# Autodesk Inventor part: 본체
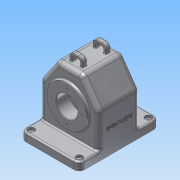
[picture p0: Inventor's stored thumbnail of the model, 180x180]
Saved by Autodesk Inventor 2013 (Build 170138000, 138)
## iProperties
Created: 2016-12
Part Number: 본체
Material: 알루미늄 6061
Document SubType Name: Modeling
Designer: Administrator
Density: 2.71 g/cm^3
Mass: 1063.78 g
Surface Area: 1146.71 cm^2
Volume: 392.539 cm^3
Author: Administrator
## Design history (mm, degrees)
sketch "스케치1"
  geometry: L1 (-65, 55)-(65, 55); L2 (75, 45)-(75, -45); L3 (65, -55)-(-65, -55); L4 (-75, -45)-(-75, 45); A1 r 10 centre (-65, 45) between (-65, 55) and (-75, 45); A2 r 10 centre (65, 45) between (75, 45) and (65, 55); A3 r 10 centre (-65, -45) between (-75, -45) and (-65, -55); A4 r 10 centre (65, -45) between (65, -55) and (75, -45); 6 further points
  constraints: 8 end point, 8 point on circle, 8 tangent, 6 point on line, 4 centre point, 3 equal radius, 2 midpoint, 2 parallel, 1 horizontal, 1 horizontal alignment, 1 perpendicular, 1 vertical alignment
  dimensions: "d0" = 150 distance of point (-75, 55) point (75, 55); "d2" = 110 distance of point (75, 55) point (75, -55); "d3" = 10 radius of A1
extrude "돌출1" new body sketch "스케치1" distance "d4" = 15; taper "d5" = 0 deg
sketch "스케치2"
  geometry: L1 (-55, 0)-(-55, 15) reference; L2 (-55, 15)-(55, 15) reference; L3 (55, 15)-(55, 0) reference; L4 (55, 0)-(-55, 0) reference; L5 (-55, 15)-(-55, 80); L6 (-23.491, 125)-(23.491, 125); L7 (55, 80)-(55, 15); L8 (-23.491, 125)-(-55, 80); L9 (23.491, 125)-(55, 80); 3 further points
  constraints: 10 end point, 2 midpoint, 2 perpendicular, 1 horizontal alignment, 1 point on line, 1 vertical, 1 vertical alignment
  dimensions: "d6" = 125 distance between parallel lines of L4 L6; "d7" = 80 distance from line of L7.start L4; "d24" = 35 deg angle of L5 L8; "d25" = 35 deg angle of L7 L9
extrude "돌출2" join sketch "스케치2" stored distance "d12" = 77; taper "d13" = 0 deg
sketch "스케치3"
  geometry: L1 (-15, -55)-(-15, 55) reference; L2 (-80, 55)-(-15, 55) reference; L3 (-15, -55)-(-80, -55) reference; L4 (0, -55)-(-15, -55) reference; L5 (0, 55)-(0, -55) reference; L6 (-15, 55)-(0, 55) reference; L7 (-125, -23.491)-(-125, 23.491) reference; L8 (-125, 23.491)-(-80, 55) reference; L9 (-80, -55)-(-125, -23.491) reference; C1 r 37.5 at (-65, 0); 2 further points
  constraints: 1 centre point, 1 horizontal alignment, 1 midpoint
  dimensions: "d15" = 65 distance from line of L5 C1.centre; "d16" = 75 diameter of C1
extrude "돌출3" join sketch "스케치3" distance "d17" = 5; taper "d18" = 0 deg
sketch "스케치4"
  geometry: L1 (15, 55)-(15, -55) reference; L2 (80, -55)-(15, -55) reference; L3 (15, 55)-(80, 55) reference; L4 (0, 55)-(15, 55) reference; L5 (0, -55)-(0, 55) reference; L6 (15, -55)-(0, -55) reference; L7 (125, 23.491)-(125, -23.491) reference; L8 (125, -23.491)-(80, -55) reference; L9 (80, 55)-(125, 23.491) reference; C1 r 31 at (65, 0); 2 further points
  constraints: 1 centre point, 1 horizontal alignment, 1 midpoint
  dimensions: "d19" = 62 diameter of C1; "d21" = 65 distance of point (0, 0) C1.centre
extrude "돌출4" join sketch "스케치4" distance "d22" = 10; taper "d23" = 0 deg
sketch "스케치6"
  geometry: L1 (-23.491, 125)-(23.491, 125) reference; L2 (23.491, 125)-(55, 80) reference; L3 (55, 80)-(55, 0) reference; L4 (55, 0)-(-55, 0) reference; L5 (-55, 0)-(-55, 80) reference; L6 (-55, 80)-(-23.491, 125) reference; L7 (50, 78.424)-(20.888, 120); L8 (20.888, 120)-(-20.888, 120); L9 (-20.888, 120)-(-50, 78.424); L10 (-50, 78.424)-(-50, 0); L11 (50, 0)-(50, 78.424); 1 further point
  constraints: 10 end point, 2 point on line, 2 other
  dimensions: "d26" = 5 distance between parallel lines of L1 L8; "d27" = 5 distance between parallel lines of L5 L10; "d28" = 5 distance between parallel lines of L11 L3
extrude "돌출5" cut sketch "스케치6" stored distance "d29" = 67; taper "d30" = 0 deg
sketch "스케치7"
  geometry: L1 (-33.5, 78.424)-(-33.5, 0) reference; L2 (-33.5, 120)-(-33.5, 78.424) reference; L3 (-43.5, 102.5)-(-43.5, 27.5) reference; L4 (33.5, 0)-(-33.5, 0) reference; L5 (-38.5, 65)-(-19.5, 65); L6 (-38.5, 111)-(-19.5, 92); L7 (-19.5, 92)-(-19.5, 65); L8 (-38.5, 125)-(-38.5, 80) reference; L9 (-38.5, 111)-(-38.5, 65); 2 further points
  constraints: 8 end point, 1 collinear, 1 horizontal alignment, 1 midpoint, 1 parallel, 1 perpendicular, 1 point on line
  dimensions: "d39" = 24 distance between parallel lines of L7 L3; "d40" = 54 diameter of L6.end L5; "d41" = 45 deg angle of L7 L6
revolve "회전1" sketch "스케치7" stored, may be unused: angle "d42" = 90 deg
hole "구멍1" diameter "d45" = 40; stored, may be unused: countersink angle "d49" = 90 deg, drill point angle "d51" = 0 deg; dims "d43" = 10, "d44" = 10, "d46" = 6, "d47" = 4, "d48" = 2, "d50" = 8
hole "구멍2" diameter "d54" = 5; stored, may be unused: countersink angle "d58" = 90 deg, drill point angle "d60" = 0 deg; dims "d52" = 10, "d53" = 10, "d55" = 6, "d56" = 12, "d57" = 5, "d59" = 8
hole "구멍3" diameter "d63" = 5; stored, may be unused: countersink angle "d67" = 90 deg, drill point angle "d69" = 0 deg; dims "d61" = 10, "d62" = 10, "d64" = 6, "d65" = 12, "d66" = 5, "d68" = 8
hole "구멍4" diameter "d72" = 5; stored, may be unused: countersink angle "d76" = 90 deg, drill point angle "d78" = 0 deg; dims "d70" = 10, "d71" = 10, "d73" = 6, "d74" = 12, "d75" = 5, "d77" = 8
hole "구멍5" diameter "d81" = 5; stored, may be unused: countersink angle "d85" = 90 deg, drill point angle "d87" = 0 deg; dims "d79" = 10, "d80" = 10, "d82" = 6, "d83" = 12, "d84" = 5, "d86" = 8
node "작업 평면1"
sketch "스케치9"
  geometry: L1 (103.5, -15)-(103.5, -80) reference; L2 (130, 0)-(0, 0) reference; 3 further points
  constraints: 1 coincident, 1 other
  dimensions: "d102" = 38.5 distance from line of point (65, -45) L1; "d103" = 45 distance from line of L2 point (65, -45)
feature "엠보싱1" sketch "스케치9" dims "d6" = 125, "d7" = 80, "d24" = 35 deg, "d25" = 35 deg, "d104" = 0.5, "d105" = 0
chamfer "모따기1" distance "d106" = 1; stored, may be unused: second distance "d107" = 2, angle "d108" = 45 deg
chamfer "모따기2" distance "d109" = 1; stored, may be unused: second distance "d110" = 2, angle "d111" = 45 deg
fillet "모깎기3" dims "d113" = 10
fillet "모깎기4" dims "d114" = 10
fillet "모깎기5" dims "d115" = 8
sketch "스케치10" dims "d116" = 52
  geometry: C1 r 31 at (0, 0) reference; 3 further points
  constraints: 2 horizontal alignment, 1 coincident, 2 other
hole "구멍6" sketch "스케치10" at (26, 0) diameter "d118" = 2.459; stored, may be unused: countersink angle "d122" = 90 deg, drill point angle "d124" = 118 deg; dims "d119" = 6, "d120" = 12, "d121" = 5, "d123" = 8
sketch "스케치11" dims "d128" = 58
  geometry: C1 r 27 at (0, 0) reference; C2 r 41 at (0, 0) reference; 3 further points
  constraints: 2 horizontal alignment, 1 coincident, 2 other
hole "구멍7" sketch "스케치11" at (-29, 0) diameter "d130" = 2.459; stored, may be unused: countersink angle "d134" = 90 deg, drill point angle "d136" = 118 deg; dims "d131" = 6, "d132" = 12, "d133" = 5, "d135" = 8
fillet "모깎기6" dims "d140" = 3
fillet "모깎기7" dims "d141" = 3
fillet "모깎기8" dims "d142" = 3
fillet "모깎기9" dims "d143" = 3
fillet "모깎기11" dims "d145" = 3
fillet "모깎기12" dims "d146" = 3
fillet "모깎기13" dims "d147" = 3
fillet "모깎기14" dims "d148" = 3
node "작업 평면2"
sketch "스케치12"
  geometry: L1 (-76.847, 55)-(0, 55) reference; L2 (0, 55)-(0, 50) reference; L3 (0, 50)-(-77.478, 50) reference; L4 (-79.198, 49.457)-(-118.721, 21.784) reference; L5 (-120, 19.326)-(-120, -19.326) reference; L6 (-118.721, -21.784)-(-79.198, -49.457) reference; L7 (-77.478, -50)-(0, -50) reference; L8 (0, -50)-(0, -55) reference; L9 (0, -55)-(-76.847, -55) reference; L10 (-82.583, -53.192)-(-120.736, -26.477) reference; L11 (-125, -18.285)-(-125, 18.285) reference; L12 (-120.736, 26.477)-(-82.583, 53.192) reference; L13 (-125, -12.5)-(-132, -12.5); L14 (-140, -4.5)-(-140, 4.5); L15 (-132, 12.5)-(-125, 12.5); L16 (0, 47)-(0, -47) reference; L17 (-125, 7.5)-(-132, 7.5); L18 (-135, 4.5)-(-135, -4.5); L19 (-132, -7.5)-(-125, -7.5); C1 r 33.5 at (-65, 0) reference; C2 r 20 at (-65, 0) reference; A1 r 3 centre (-77.478, 47) between (-77.478, 50) and (-79.198, 49.457) reference; A2 r 3 centre (-117, 19.326) between (-118.721, 21.784) and (-120, 19.326) reference; A3 r 3 centre (-117, -19.326) between (-120, -19.326) and (-118.721, -21.784) reference; A4 r 3 centre (-77.478, -47) between (-79.198, -49.457) and (-77.478, -50) reference; A5 r 10 centre (-76.847, -45) between (-82.583, -53.192) and (-76.847, -55) reference; A6 r 10 centre (-115, -18.285) between (-125, -18.285) and (-120.736, -26.477) reference; A7 r 10 centre (-115, 18.285) between (-120.736, 26.477) and (-125, 18.285) reference; A8 r 10 centre (-76.847, 45) between (-76.847, 55) and (-82.583, 53.192) reference; A9 r 8 centre (-132, -4.5) between (-140, -4.5) and (-132, -12.5); A10 r 8 centre (-132, 4.5) between (-132, 12.5) and (-140, 4.5); A11 r 3 centre (-132, 4.5) between (-132, 7.5) and (-135, 4.5); A12 r 3 centre (-132, -4.5) between (-135, -4.5) and (-132, -7.5); 5 further points
  constraints: 12 end point, 8 point on circle, 8 point on line, 4 centre point, 4 tangent, 2 midpoint, 1 equal radius, 1 horizontal, 1 horizontal alignment, 1 perpendicular, 1 vertical, 4 other
  dimensions: "d150" = 25 distance of point (-140, -12.5) point (-140, 12.5); "d151" = 140 distance between parallel lines of L16 L14; "d152" = 8 radius of A9; "d153" = 5 distance between parallel lines of L14 L18; "d154" = 15 distance between parallel lines of L17 L19 (derived)
extrude "돌출7" join sketch "스케치12" distance "d155" = 8; taper "d156" = 0 deg
fillet "모깎기15" dims "d157" = 1
fillet "모깎기16" dims "d158" = 1
node "솔리드1"
pattern_circular "원형 패턴1" dims angle "d126" = 360 deg
pattern_circular "원형 패턴2" dims angle "d138" = 360 deg
mirror "대칭2"
node "투영된 루프1"
node "절단 모서리 투영1"
node "절단 모서리 투영2"
node "절단 모서리 투영3"
node "절단 모서리 투영4"
node "절단 모서리 투영6"
other parameters: "d88" = -10.5, "d149" = -12.5
